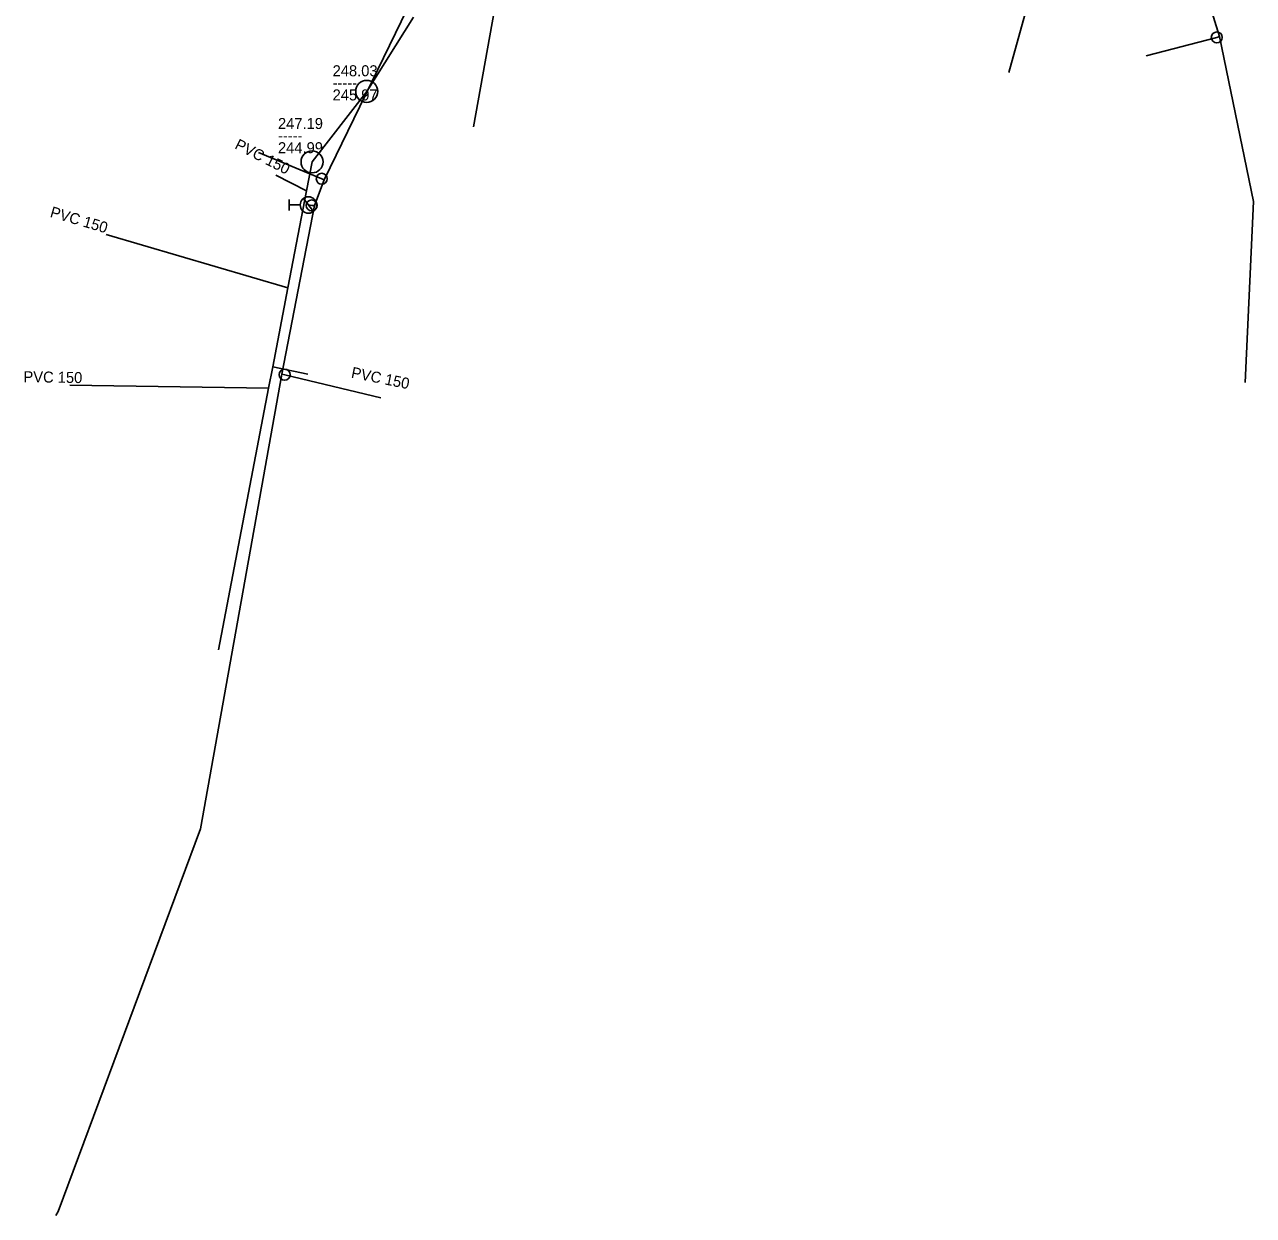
# Model space of a CAD drawing. Extents: x -771681 to -770485, y -1050143 to -1049574.
# Drawn here: x -770725.9 to -770614.1, y -1050142.9 to -1050034.6 of the extents above; entities that cross this region are included whole.
import ezdxf

# ---------------------------------------------------------------- set-up
doc = ezdxf.new("R2010")
doc.units = 0
doc.layers.add('Level 0', color=7, linetype='Continuous')

msp = doc.modelspace()

# ---------------------------------------------------------------- linework, layer by layer
at = {"layer": 'Level 0'}
for p, q in [((-770617.23, -1050035.68), (-770624.58, -1050011.72)), ((-770631.87, -1050022.72), (-770636.39, -1050038.95)), ((-770698.66, -1050048.72), (-770686.45, -1050023.6)), ((-770682.09, -1050027.16), (-770685.08, -1050043.91)), ((-770690.52, -1050033.93), (-770694.79, -1050040.68)), ((-770617.46, -1050035.77), (-770623.9, -1050037.43)), ((-770617.23, -1050035.68), (-770617.46, -1050035.77)), ((-770614.13, -1050050.69), (-770617.23, -1050035.68)), ((-770694.79, -1050040.68), (-770699.76, -1050047.09)), ((-770698.88, -1050048.63), (-770704.64, -1050046.25)), ((-770699.76, -1050047.09), (-770700.26, -1050049.71)), ((-770700.26, -1050049.71), (-770703.05, -1050048.29)), ((-770698.66, -1050048.72), (-770698.88, -1050048.63)), ((-770700.26, -1050049.71), (-770701.96, -1050058.56)), ((-770699.54, -1050051.07), (-770698.66, -1050048.72)), ((-770701.84, -1050051.51), (-770701.84, -1050050.51)), ((-770699.63, -1050051.6), (-770700.55, -1050050.42)), ((-770614.88, -1050067.15), (-770614.13, -1050050.69)), ((-770702.51, -1050066.39), (-770699.54, -1050051.07)), ((-770700.84, -1050051.01), (-770701.84, -1050051.01)), ((-770699.79, -1050051.05), (-770700.09, -1050051.01)), ((-770699.54, -1050051.07), (-770699.79, -1050051.05)), ((-770701.96, -1050058.56), (-770718.5, -1050053.69)), ((-770701.96, -1050058.56), (-770703.34, -1050065.74)), ((-770709.92, -1050107.76), (-770702.51, -1050066.39)), ((-770703.34, -1050065.74), (-770703.71, -1050067.68)), ((-770703.34, -1050065.74), (-770700.13, -1050066.39)), ((-770702.51, -1050066.39), (-770702.25, -1050066.45)), ((-770702.25, -1050066.45), (-770693.49, -1050068.56)), ((-770703.71, -1050067.68), (-770721.78, -1050067.39)), ((-770703.71, -1050067.68), (-770708.28, -1050091.49)), ((-770722.87, -1050142.58), (-770709.92, -1050107.76)), ((-770723.06, -1050142.93), (-770722.87, -1050142.58))]:
    msp.add_line(p, q, dxfattribs=at)
for centre, radius in [((-770617.46, -1050035.77), 0.5), ((-770694.79, -1050040.68), 1), ((-770699.76, -1050047.09), 1), ((-770698.88, -1050048.63), 0.5), ((-770700.09, -1050051.01), 0.75), ((-770699.79, -1050051.05), 0.5), ((-770702.25, -1050066.45), 0.5)]:
    msp.add_circle(centre, radius, dxfattribs=at)

# ---------------------------------------------------------------- texts
for s, p in [('248.03', (-770697.89, -1050039.3)), ('-----', (-770697.89, -1050040.4)), ('245.97', (-770697.89, -1050041.5)), ('247.19', (-770702.86, -1050044.1)), ('-----', (-770702.86, -1050045.2)), ('244.99', (-770702.86, -1050046.3))]:
    msp.add_text(s, height=1, dxfattribs=at).set_placement(p)
for rotation, p in [(333.026, (-770706.87, -1050045.84)), (343.594, (-770723.66, -1050052.08)), (359.081, (-770726.02, -1050067.13)), (348.553, (-770696.26, -1050066.71))]:
    msp.add_text('PVC 150', height=1, rotation=rotation, dxfattribs=at).set_placement(p)

doc.saveas('drawing.dxf')
